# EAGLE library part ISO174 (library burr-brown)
Isolated Amplifier
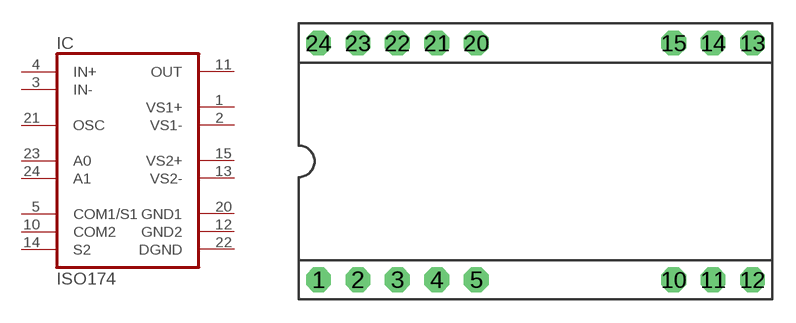
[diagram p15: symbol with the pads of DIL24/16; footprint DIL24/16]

Designator prefix IC

## ISO174P (OC_FARNELL: unknown; OC_NEWARK: unknown)  [DIL24/16]
1  VS1+  pwr
2  VS1-  pwr
3  IN-  in
4  IN+  in
5  COM1/S1  pas
10  COM2  pas
11  OUT  out
12  GND2  pwr
13  VS2-  pwr
14  S2  pas
15  VS2+  pwr
20  GND1  pwr
21  OSC  in
22  DGND  pwr
23  A0  pas
24  A1  pas

## Footprint DIL24/16 (pad centres in mm)
Dual In Line
drill 0.813 pad 1.6 octagon: 1 -13.97,-7.62; 2 -11.43,-7.62; 3 -8.89,-7.62; 4 -6.35,-7.62; 5 -3.81,-7.62; 10 8.89,-7.62; 11 11.43,-7.62; 12 13.97,-7.62; 13 13.97,7.62; 14 11.43,7.62; 15 8.89,7.62; 20 -3.81,7.62; 21 -6.35,7.62; 22 -8.89,7.62; 23 -11.43,7.62; 24 -13.97,7.62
